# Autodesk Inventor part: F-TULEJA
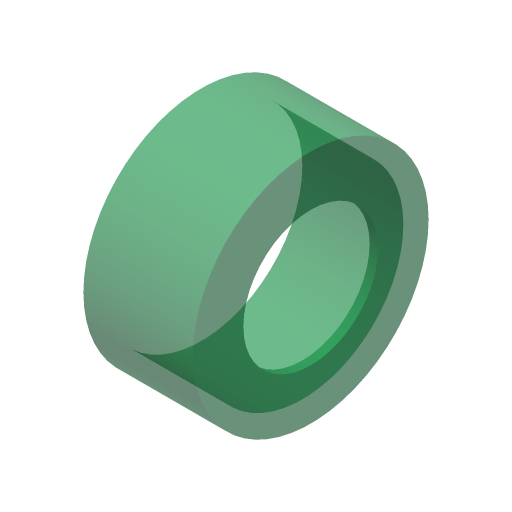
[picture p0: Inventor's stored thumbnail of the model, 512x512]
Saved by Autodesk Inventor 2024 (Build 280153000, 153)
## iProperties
Company: ATC
Created: 2023-03
Part Number: F-TULEJA
Document SubType Name: Modeling
Designer: Andrzej Jaskulski
Manufacturer: Standard
Standards Organization: Custom
Density: 1 g/cm^3
Material: Ogólny
Appearance: Przezroczyste - zielone 1
Checked By: A.J.
Engr Approved By: Andrzej Jaskulski
Mfg Approved By: Andrzej Jaskulski
Authority: A.J.
Title: A.J.: Kurs R2024-MEP
Author: Andrzej Jaskulski
Revision Number: 1/24
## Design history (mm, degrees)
sketch "Szkic1"
  geometry: C1 r 4 at (0, 0) reference; C2 r 6 at (0, 0) reference; C3 r 7 at (0, 0)
  constraints: 1 centre point, 1 coincident
  dimensions: "d4" = 1 radial gap between concentric circles of C3 C2
extrude "Wyciągnięcie proste1" new body sketch "Szkic1" distance "d0" = 6; taper "d1" = 0 deg
extrude "Wyciągnięcie proste2" join sketch "Szkic1" distance "d2" = 0.5; taper "d3" = 0 deg
node "Bryła1"
node "Korpusy bryłowe"
node "Korpusy powierzchniowe"
